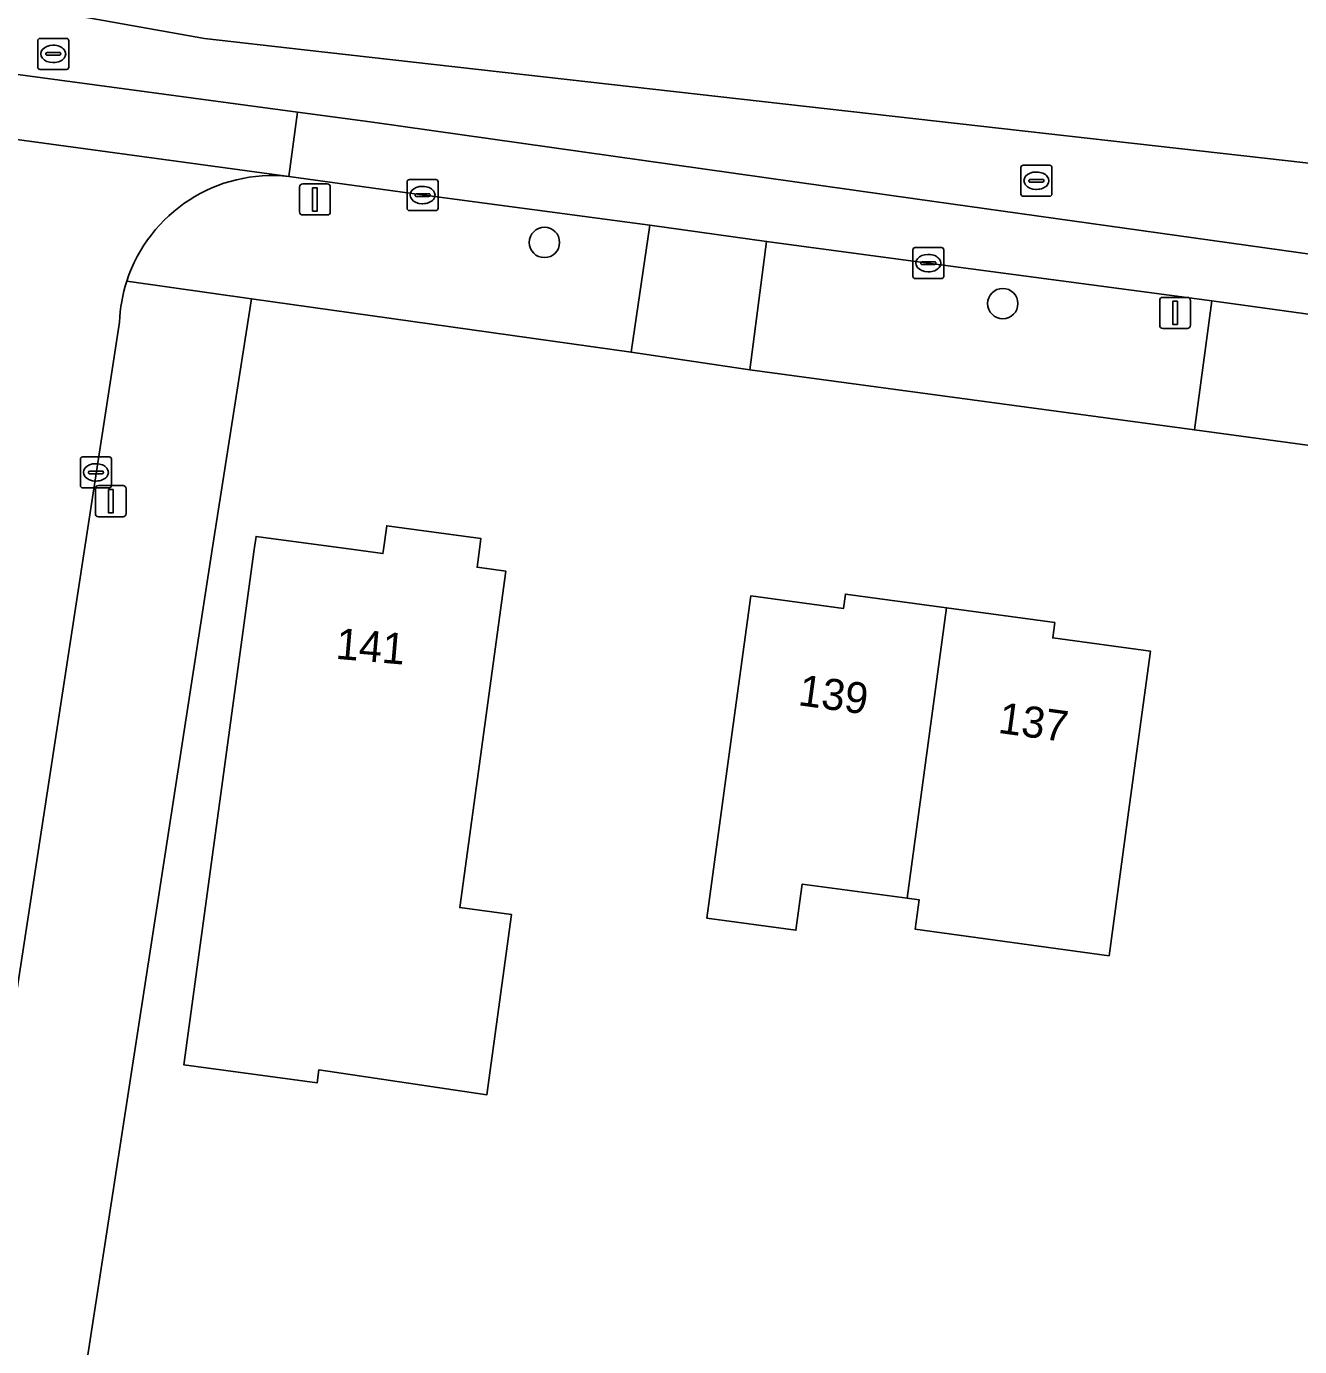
# Model space of a CAD drawing. Extents: x 161483 to 162250, y 379484 to 380833.
# Drawn here: x 162146.57 to 162187.6, y 380724.32 to 380766.86 of the extents above; entities that cross this region are included whole.
import ezdxf

# ---------------------------------------------------------------- set-up
doc = ezdxf.new("R2010")
doc.units = 0
for name, color, linetype in [('IMGEO_Boom', 7, 'Continuous'), ('IMGEO_Erf', 7, 'Continuous'), ('IMGEO_Fietspad_gesloten', 7, 'Continuous'), ('IMGEO_Kolk', 7, 'Continuous'), ('IMGEO_Lichtmast', 7, 'Continuous'), ('IMGEO_Pand', 7, 'Continuous'), ('IMGEO_Pand_nummerreeks', 7, 'Continuous'), ('IMGEO_Rijbaan_lokaal_gesloten', 7, 'Continuous'), ('IMGEO_Rijbaan_lokaal_open', 7, 'Continuous'), ('IMGEO_Rioolput', 7, 'Continuous'), ('IMGEO_Voetpad_open', 7, 'Continuous')]:
    doc.layers.add(name, color=color, linetype=linetype)

msp = doc.modelspace()

# ---------------------------------------------------------------- linework, layer by layer
at = {"layer": 'IMGEO_Boom'}
for centre in [(162163.269, 380759.9), (162178.039, 380757.93)]:
    msp.add_circle(centre, 0.489, dxfattribs=at)
at = {"layer": 'IMGEO_Erf'}
msp.add_lwpolyline([(162192.213, 380752.777), (162184.217, 380753.861), (162169.89, 380755.8), (162166.06, 380756.368), (162153.828, 380758.083), (162152.56, 380750), (162147.249, 380715.624)], dxfattribs=at)
for points in [[(162155.999, 380733.24), (162155.941, 380732.813), (162151.646, 380733.399), (162153.915, 380750), (162153.974, 380750.429), (162157.118, 380750), (162158.063, 380749.871), (162158.081, 380750), (162158.185, 380750.769), (162161.221, 380750.355), (162161.173, 380750), (162161.096, 380749.431), (162162.019, 380749.305), (162161.343, 380744.351), (162160.541, 380738.467), (162162.207, 380738.24), (162161.414, 380732.431)], [(162168.5, 380738.126), (162169.242, 380743.567), (162169.916, 380748.509), (162172.905, 380748.101), (162172.969, 380748.568), (162176.229, 380748.123), (162179.716, 380747.648), (162179.65, 380747.157), (162182.804, 380746.726), (162182.128, 380741.772), (162181.465, 380736.913), (162175.22, 380737.765), (162175.349, 380738.71), (162174.963, 380738.763), (162171.578, 380739.224), (162171.374, 380737.734)]]:
    msp.add_lwpolyline(points, close=True, dxfattribs=at)
at = {"layer": 'IMGEO_Fietspad_gesloten'}
msp.add_lwpolyline([(162155.313, 380764.1), (162139.976, 380766.161), (162139.7, 380764.105), (162155.035, 380762.03)], close=True, dxfattribs=at)
for points in [[(162157.657, 380763.785), (162155.313, 380764.1), (162155.035, 380762.03), (162159.244, 380761.443), (162166.661, 380760.453), (162170.429, 380759.935), (162175.636, 380759.235), (162184.774, 380758.023), (162192.08, 380757.004), (162196.98, 380756.34), (162207.406, 380754.917), (162214.832, 380753.916), (162216.594, 380753.666), (162220.723, 380753.037), (162221.736, 380752.9), (162222.083, 380755.44), (162217.167, 380756.124)], [(162216.737, 380756.638), (162207.5, 380757.078), (162198.829, 380757.994), (162175.214, 380761.306), (162157.657, 380763.785)]]:
    msp.add_lwpolyline(points, dxfattribs=at)
at = {"layer": 'IMGEO_Kolk'}
for p, q in [((162158.841, 380761.002), (162158.841, 380761.854)), ((162158.916, 380761.928), (162159.768, 380761.928)), ((162159.329, 380761.708), (162159.354, 380761.708)), ((162159.842, 380761.854), (162159.842, 380761.002)), ((162159.1, 380761.422), (162159.1, 380761.434)), ((162159.538, 380761.385), (162159.14, 380761.385)), ((162159.143, 380761.471), (162159.541, 380761.471)), ((162159.584, 380761.434), (162159.584, 380761.422)), ((162159.768, 380760.928), (162158.916, 380760.928)), ((162159.352, 380761.148), (162159.327, 380761.148)), ((162175.139, 380758.808), (162175.139, 380759.66)), ((162175.214, 380759.734), (162176.066, 380759.734)), ((162175.627, 380759.514), (162175.652, 380759.514)), ((162176.14, 380759.66), (162176.14, 380758.808)), ((162175.398, 380759.228), (162175.398, 380759.24)), ((162175.836, 380759.191), (162175.438, 380759.191)), ((162175.441, 380759.277), (162175.839, 380759.277)), ((162175.882, 380759.24), (162175.882, 380759.228)), ((162176.066, 380758.734), (162175.214, 380758.734)), ((162175.65, 380758.954), (162175.625, 380758.954)), ((162148.314, 380752.064), (162148.314, 380752.916)), ((162148.389, 380752.99), (162149.241, 380752.99)), ((162148.802, 380752.77), (162148.827, 380752.77)), ((162149.315, 380752.916), (162149.315, 380752.064)), ((162148.573, 380752.484), (162148.573, 380752.496)), ((162149.011, 380752.447), (162148.613, 380752.447)), ((162148.616, 380752.533), (162149.014, 380752.533)), ((162149.057, 380752.496), (162149.057, 380752.484)), ((162149.241, 380751.99), (162148.389, 380751.99)), ((162148.825, 380752.21), (162148.8, 380752.21))]:
    msp.add_line(p, q, dxfattribs=at)
for points in [[(162158.841, 380761.002), (162158.841, 380761.854)], [(162158.916, 380761.928), (162159.768, 380761.928)], [(162159.842, 380761.854), (162159.842, 380761.002)], [(162159.768, 380760.928), (162158.916, 380760.928)], [(162175.139, 380758.808), (162175.139, 380759.66)], [(162175.214, 380759.734), (162176.066, 380759.734)], [(162176.14, 380759.66), (162176.14, 380758.808)], [(162176.066, 380758.734), (162175.214, 380758.734)], [(162148.314, 380752.064), (162148.314, 380752.916)], [(162148.389, 380752.99), (162149.241, 380752.99)], [(162149.315, 380752.916), (162149.315, 380752.064)], [(162149.241, 380751.99), (162148.389, 380751.99)]]:
    msp.add_lwpolyline(points, dxfattribs=at)
for centre, radius, start, end in [((162158.918, 380761.852), 0.0765, 91.552, 178.448), ((162158.918, 380761.852), 0.0765, 91.552, 178.448), ((162159.766, 380761.852), 0.0765, 1.552, 88.448), ((162159.766, 380761.852), 0.0765, 1.552, 88.448), ((162159.14, 380761.431), 0.0403, 85.8775, 175.7526), ((162159.137, 380761.421), 0.0366, 178.938, 274.7102), ((162159.541, 380761.428), 0.043, 264.8664, 352.4533), ((162159.545, 380761.433), 0.0386, 1.7309, 96.639), ((162158.918, 380761.004), 0.0765, 181.552, 268.448), ((162158.918, 380761.004), 0.0765, 181.552, 268.448), ((162159.766, 380761.004), 0.0765, 271.552, 358.448), ((162159.766, 380761.004), 0.0765, 271.552, 358.448), ((162175.216, 380759.658), 0.0765, 91.552, 178.448), ((162175.216, 380759.658), 0.0765, 91.552, 178.448), ((162176.064, 380759.658), 0.0765, 1.552, 88.448), ((162176.064, 380759.658), 0.0765, 1.552, 88.448), ((162175.438, 380759.237), 0.0403, 85.8775, 175.7526), ((162175.435, 380759.227), 0.0366, 178.938, 274.7102), ((162175.839, 380759.234), 0.043, 264.8664, 352.4533), ((162175.843, 380759.239), 0.0386, 1.7309, 96.639), ((162175.216, 380758.81), 0.0765, 181.552, 268.448), ((162175.216, 380758.81), 0.0765, 181.552, 268.448), ((162176.064, 380758.81), 0.0765, 271.552, 358.448), ((162176.064, 380758.81), 0.0765, 271.552, 358.448), ((162148.391, 380752.914), 0.0765, 91.552, 178.448), ((162148.391, 380752.914), 0.0765, 91.552, 178.448), ((162149.239, 380752.914), 0.0765, 1.552, 88.448), ((162149.239, 380752.914), 0.0765, 1.552, 88.448), ((162148.613, 380752.493), 0.0403, 85.8775, 175.7526), ((162148.61, 380752.483), 0.0366, 178.938, 274.7102), ((162149.014, 380752.49), 0.043, 264.8664, 352.4533), ((162149.018, 380752.495), 0.0386, 1.7309, 96.639), ((162148.391, 380752.066), 0.0765, 181.552, 268.448), ((162148.391, 380752.066), 0.0765, 181.552, 268.448), ((162149.239, 380752.066), 0.0765, 271.552, 358.448), ((162149.239, 380752.066), 0.0765, 271.552, 358.448)]:
    msp.add_arc(centre, radius, start, end, dxfattribs=at)
for centre, major_axis, ratio, start_param, end_param in [((162159.328, 380761.428), (-0.387, 0.002), 0.722429, 4.712389, 7.853982), ((162159.353, 380761.428), (-0.39, 0.002), 0.717154, 1.570796, 4.712389), ((162175.626, 380759.234), (-0.387, 0.002), 0.722429, 4.712389, 7.853982), ((162175.651, 380759.234), (-0.39, 0.002), 0.717154, 1.570796, 4.712389), ((162148.801, 380752.49), (-0.387, 0.002), 0.722429, 4.712389, 7.853982), ((162148.826, 380752.49), (-0.39, 0.002), 0.717154, 1.570796, 4.712389)]:
    msp.add_ellipse(centre, major_axis=major_axis, ratio=ratio, start_param=start_param, end_param=end_param, dxfattribs=at)
at = {"layer": 'IMGEO_Lichtmast'}
for p, q in [((162155.377, 380760.885), (162155.377, 380761.685)), ((162155.377, 380761.685), (162155.377, 380760.885)), ((162155.477, 380761.785), (162156.267, 380761.785)), ((162156.267, 380761.785), (162155.477, 380761.785)), ((162156.367, 380761.685), (162156.367, 380760.885)), ((162156.367, 380760.885), (162156.367, 380761.685)), ((162156.267, 380760.785), (162155.477, 380760.785)), ((162155.477, 380760.785), (162156.267, 380760.785)), ((162183.097, 380757.231), (162183.097, 380758.031)), ((162183.097, 380758.031), (162183.097, 380757.231)), ((162183.197, 380758.131), (162183.987, 380758.131)), ((162183.987, 380758.131), (162183.197, 380758.131)), ((162184.087, 380758.031), (162184.087, 380757.231)), ((162184.087, 380757.231), (162184.087, 380758.031)), ((162183.987, 380757.131), (162183.197, 380757.131)), ((162183.197, 380757.131), (162183.987, 380757.131)), ((162148.798, 380751.162), (162148.798, 380751.962)), ((162148.798, 380751.962), (162148.798, 380751.162)), ((162148.898, 380752.062), (162149.688, 380752.062)), ((162149.688, 380752.062), (162148.898, 380752.062)), ((162149.788, 380751.962), (162149.788, 380751.162)), ((162149.788, 380751.162), (162149.788, 380751.962)), ((162149.688, 380751.062), (162148.898, 380751.062)), ((162148.898, 380751.062), (162149.688, 380751.062))]:
    msp.add_line(p, q, dxfattribs=at)
for points in [[(162155.797, 380761.66), (162155.947, 380761.66), (162155.947, 380760.91), (162155.797, 380760.91), (162155.797, 380761.66)], [(162183.517, 380758.006), (162183.667, 380758.006), (162183.667, 380757.256), (162183.517, 380757.256), (162183.517, 380758.006)], [(162149.218, 380751.937), (162149.368, 380751.937), (162149.368, 380751.187), (162149.218, 380751.187), (162149.218, 380751.937)]]:
    msp.add_lwpolyline(points, dxfattribs=at)
for centre, start, end in [((162155.477, 380761.685), 90, 180), ((162155.477, 380761.685), 90, 180), ((162156.267, 380761.685), 0, 90), ((162156.267, 380761.685), 360, 90), ((162155.477, 380760.885), 180, 270), ((162155.477, 380760.885), 180, 270), ((162156.267, 380760.885), 270, 0), ((162156.267, 380760.885), 270, 0), ((162183.197, 380758.031), 90, 180), ((162183.197, 380758.031), 90, 180), ((162183.987, 380758.031), 0, 90), ((162183.987, 380758.031), 360, 90), ((162183.197, 380757.231), 180, 270), ((162183.197, 380757.231), 180, 270), ((162183.987, 380757.231), 270, 0), ((162183.987, 380757.231), 270, 0), ((162148.898, 380751.962), 90, 180), ((162148.898, 380751.962), 90, 180), ((162149.688, 380751.962), 0, 90), ((162149.688, 380751.962), 360, 90), ((162148.898, 380751.162), 180, 270), ((162148.898, 380751.162), 180, 270), ((162149.688, 380751.162), 270, 0), ((162149.688, 380751.162), 270, 0)]:
    msp.add_arc(centre, 0.1, start, end, dxfattribs=at)
at = {"layer": 'IMGEO_Pand'}
for points in [[(162161.343, 380744.351), (162162.019, 380749.305), (162161.096, 380749.431), (162161.173, 380750), (162161.221, 380750.355), (162158.185, 380750.769), (162158.081, 380750), (162158.063, 380749.871), (162157.118, 380750), (162153.974, 380750.429), (162153.915, 380750), (162151.646, 380733.399), (162155.941, 380732.813), (162155.999, 380733.24), (162161.414, 380732.431), (162162.207, 380738.24), (162160.541, 380738.467)], [(162176.229, 380748.123), (162172.969, 380748.568), (162172.905, 380748.101), (162169.916, 380748.509), (162169.242, 380743.567), (162168.5, 380738.126), (162171.374, 380737.734), (162171.578, 380739.224), (162174.963, 380738.763)], [(162176.229, 380748.123), (162174.963, 380738.763), (162175.349, 380738.71), (162175.22, 380737.765), (162181.465, 380736.913), (162182.128, 380741.772), (162182.804, 380746.726), (162179.65, 380747.157), (162179.716, 380747.648)]]:
    msp.add_lwpolyline(points, close=True, dxfattribs=at)
at = {"layer": 'IMGEO_Rijbaan_lokaal_gesloten'}
for points in [[(162235.883, 380761.117), (162225.793, 380762.232), (162195.841, 380761.556), (162155.522, 380766.113), (162152.312, 380766.476), (162100.246, 380775.712), (162094.38, 380775.785), (162063.3, 380779.137), (162022.247, 380782.773), (161914.65, 380797.204), (161859.959, 380804.218), (161826.791, 380811.355), (161807.579, 380816.265), (161765.369, 380823.138), (161719.379, 380829.094), (161719.203, 380827.684), (161722.585, 380827.174), (161725.837, 380826.617)], [(161833.402, 380807.634), (161845.075, 380805.921), (161887.22, 380800.191), (161944.816, 380792.342), (162034.971, 380780.165), (162056.354, 380777.224), (162056.903, 380777.191), (162081.643, 380775.785), (162086.162, 380775.288), (162093.056, 380774.264), (162108.19, 380772.217), (162118.907, 380770.062), (162138.618, 380766.344), (162139.976, 380766.161), (162155.313, 380764.1), (162157.657, 380763.785), (162175.214, 380761.306), (162198.829, 380757.994), (162207.5, 380757.078), (162216.737, 380756.638)]]:
    msp.add_lwpolyline(points, dxfattribs=at)
at = {"layer": 'IMGEO_Rijbaan_lokaal_open'}
for points in [[(162155.035, 380762.03), (162139.7, 380764.105)], [(162144.167, 380758.722), (162143.388, 380753.025), (162142.919, 380750), (162139.145, 380725.673), (162139.105, 380725.415), (162139.024, 380724.806), (162137.671, 380716.171), (162135.538, 380702.164), (162140.937, 380701.405), (162143.182, 380715.895), (162144.399, 380723.648), (162148.444, 380750)], [(162148.444, 380750), (162149.572, 380757.336)]]:
    msp.add_lwpolyline(points, dxfattribs=at)
for centre, radius, start, end in [((162154.501, 380757.125), 4.934, 83.7832, 162.0091), ((162154.554, 380757.118), 4.987, 162.1238, 177.497)]:
    msp.add_arc(centre, radius, start, end, dxfattribs=at)
at = {"layer": 'IMGEO_Rioolput'}
for p, q in [((162146.939, 380765.55), (162146.939, 380766.402)), ((162147.014, 380766.476), (162147.866, 380766.476)), ((162147.94, 380766.402), (162147.94, 380765.55)), ((162147.198, 380765.97), (162147.198, 380765.982)), ((162147.636, 380765.933), (162147.238, 380765.933)), ((162147.241, 380766.019), (162147.639, 380766.019)), ((162147.427, 380766.256), (162147.452, 380766.256)), ((162147.682, 380765.982), (162147.682, 380765.97)), ((162147.866, 380765.476), (162147.014, 380765.476)), ((162147.45, 380765.696), (162147.425, 380765.696)), ((162178.623, 380761.464), (162178.623, 380762.316)), ((162178.698, 380762.39), (162179.55, 380762.39)), ((162179.111, 380762.17), (162179.136, 380762.17)), ((162179.624, 380762.316), (162179.624, 380761.464)), ((162178.882, 380761.884), (162178.882, 380761.896)), ((162179.32, 380761.847), (162178.922, 380761.847)), ((162178.925, 380761.933), (162179.323, 380761.933)), ((162179.366, 380761.896), (162179.366, 380761.884)), ((162179.55, 380761.39), (162178.698, 380761.39)), ((162179.134, 380761.61), (162179.109, 380761.61))]:
    msp.add_line(p, q, dxfattribs=at)
for points in [[(162146.939, 380765.55), (162146.939, 380766.402)], [(162147.014, 380766.476), (162147.866, 380766.476)], [(162147.94, 380766.402), (162147.94, 380765.55)], [(162147.866, 380765.476), (162147.014, 380765.476)], [(162178.623, 380761.464), (162178.623, 380762.316)], [(162178.698, 380762.39), (162179.55, 380762.39)], [(162179.624, 380762.316), (162179.624, 380761.464)], [(162179.55, 380761.39), (162178.698, 380761.39)]]:
    msp.add_lwpolyline(points, dxfattribs=at)
for centre, radius, start, end in [((162147.016, 380766.4), 0.0765, 91.552, 178.448), ((162147.016, 380766.4), 0.0765, 91.552, 178.448), ((162147.864, 380766.4), 0.0765, 1.552, 88.448), ((162147.864, 380766.4), 0.0765, 1.552, 88.448), ((162147.238, 380765.979), 0.0403, 85.8775, 175.7526), ((162147.235, 380765.969), 0.0366, 178.938, 274.7102), ((162147.639, 380765.976), 0.043, 264.8664, 352.4533), ((162147.643, 380765.981), 0.0386, 1.7309, 96.639), ((162147.016, 380765.552), 0.0765, 181.552, 268.448), ((162147.016, 380765.552), 0.0765, 181.552, 268.448), ((162147.864, 380765.552), 0.0765, 271.552, 358.448), ((162147.864, 380765.552), 0.0765, 271.552, 358.448), ((162178.7, 380762.314), 0.0765, 91.552, 178.448), ((162178.7, 380762.314), 0.0765, 91.552, 178.448), ((162179.548, 380762.314), 0.0765, 1.552, 88.448), ((162179.548, 380762.314), 0.0765, 1.552, 88.448), ((162178.922, 380761.893), 0.0403, 85.8775, 175.7526), ((162178.919, 380761.883), 0.0366, 178.938, 274.7102), ((162179.323, 380761.89), 0.043, 264.8664, 352.4533), ((162179.327, 380761.895), 0.0386, 1.7309, 96.639), ((162178.7, 380761.466), 0.0765, 181.552, 268.448), ((162178.7, 380761.466), 0.0765, 181.552, 268.448), ((162179.548, 380761.466), 0.0765, 271.552, 358.448), ((162179.548, 380761.466), 0.0765, 271.552, 358.448)]:
    msp.add_arc(centre, radius, start, end, dxfattribs=at)
for centre, major_axis, ratio, start_param, end_param in [((162147.426, 380765.976), (-0.387, 0.002), 0.722429, 4.712389, 7.853982), ((162147.451, 380765.976), (-0.39, 0.002), 0.717154, 1.570796, 4.712389), ((162179.11, 380761.89), (-0.387, 0.002), 0.722429, 4.712389, 7.853982), ((162179.135, 380761.89), (-0.39, 0.002), 0.717154, 1.570796, 4.712389)]:
    msp.add_ellipse(centre, major_axis=major_axis, ratio=ratio, start_param=start_param, end_param=end_param, dxfattribs=at)
at = {"layer": 'IMGEO_Voetpad_open'}
for points in [[(162166.661, 380760.453), (162159.244, 380761.443), (162155.035, 380762.03)], [(162149.808, 380758.649), (162153.828, 380758.083), (162166.06, 380756.368), (162166.661, 380760.453)], [(162142.65, 380686.805), (162142.667, 380686.916), (162143.178, 380690.285), (162143.388, 380690.241), (162147.249, 380715.624), (162152.56, 380750), (162153.828, 380758.083), (162149.808, 380758.649)], [(162149.572, 380757.336), (162148.444, 380750), (162144.399, 380723.648), (162144.892, 380723.571), (162143.675, 380715.818), (162143.182, 380715.895), (162140.937, 380701.405), (162140.517, 380698.694), (162139.304, 380690.868), (162139.798, 380690.792), (162139.247, 380687.221), (162138.753, 380687.297), (162130.113, 380630.707), (162130.012, 380630.045), (162129.701, 380628.045), (162123.558, 380588.489), (162124.052, 380588.415), (162123.504, 380584.802), (162123.01, 380584.876), (162120.667, 380569.693), (162120.252, 380567.006), (162118.66, 380556.689)]]:
    msp.add_lwpolyline(points, dxfattribs=at)
for points in [[(162169.89, 380755.8), (162170.429, 380759.935), (162166.661, 380760.453), (162166.06, 380756.368)], [(162184.217, 380753.861), (162184.774, 380758.023), (162175.636, 380759.235), (162170.429, 380759.935), (162169.89, 380755.8)], [(162192.213, 380752.777), (162192.588, 380755.346), (162191.883, 380755.484), (162192.08, 380757.004), (162184.774, 380758.023), (162184.217, 380753.861)]]:
    msp.add_lwpolyline(points, close=True, dxfattribs=at)
for centre, radius, start, end in [((162154.501, 380757.125), 4.934, 83.7832, 162.0091), ((162154.554, 380757.118), 4.987, 162.1238, 177.497)]:
    msp.add_arc(centre, radius, start, end, dxfattribs=at)

# ---------------------------------------------------------------- texts
at = {"layer": 'IMGEO_Pand_nummerreeks'}
for s, rotation, p in [('141', 355.0955, (162156.518, 380746.484)), ('139', 352.1234, (162171.414, 380744.991)), ('137', 352.1234, (162177.858, 380744.099))]:
    msp.add_text(s, height=1, rotation=rotation, dxfattribs=at).set_placement(p)

doc.saveas('drawing.dxf')
